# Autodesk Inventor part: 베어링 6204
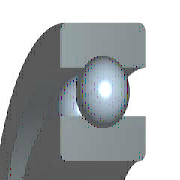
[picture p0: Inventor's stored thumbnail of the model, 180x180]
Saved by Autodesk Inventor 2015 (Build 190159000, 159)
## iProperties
Created: 2012-02
Part Number: 베어링 6204
Material: 강철, 연강
Description: 깊은 그루브 볼 베어링
Document SubType Name: Modeling
Standard: KS B 2023
Designer: mduedu
Standards Organization: KS
Language: ko-KR
Size Designation: 6203 - 17 x 40 x 12
Categories: <MemberInstance><Categories><Category DisplayName="샤프트 부품" InternalName="7f7aeb1f-a693-4053-b835-cee3144e0d98" Mnemonic="SHFT"><Category DisplayName="베어링" Inter
Density: 1 g/cm^3
Appearance: 노란색
IsCustomPart: 1
Author: mduedu
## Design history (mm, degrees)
sketch "스케치" dims "d0" = 7.02 (= -0.26 x WD + 0.26 x BD)
  geometry: L1 (3.49, 16.75)-(10.51, 16.75); L2 (7, 16.75)-(7, 13.24); L3 (7, 16.75)-(7, 20.26); L4 (4.392, 14.401)-(0, 14.401); L5 (0, 10)-(14, 10); L6 (4.392, 19.099)-(0, 19.099); L7 (0, 23.5)-(14, 23.5); L8 (14, 10)-(14, 14.401); L9 (9.608, 14.401)-(14, 14.401); L10 (9.608, 19.099)-(14, 19.099); L11 (14, 23.5)-(14, 19.099); L12 (-2.4, 0)-(14.4, 0) reference; L13 (0, 7.3)-(0, 26.2) reference
  constraints: 22 end point, 4 point on line, 2 collinear, 2 perpendicular, 2 symmetric about line, 1 midpoint, 1 parallel, 14 other
  dimensions: "d9" = 20 diameter of L5 L12 (= WD); "d11" = 47 diameter of L7 L12 (= BD); "d12" = 14 distance between parallel lines of L8 L13 (= KB); "d13" = 28.802 diameter of L9 L12 (= 0.326 x BD + 0.674 x WD)
revolve "본체" stored, may be unused: angle "d6" = 90 deg
revolve "볼" stored, may be unused: angle "d7" = 90 deg
pattern_circular "IDS_ARRAYBALL[SIMPL:T]" dims angle "d3" = 360 deg
body "Solid1"
fillet "모깎기1" dims "d1" = 1 (= KRS)
other parameters: "WD" = 20 [user parameter; used in 5 equation terms], "BD" = 47 [user parameter; used in 5 equation terms], "KB" = 14 [user parameter; used in 1 equation term], "KRS" = 1 [user parameter; used in 1 equation term], "d4" = 0, "d5" = 0, "d8" = 0, "d14" = 0, "d15" = 0, "BBA" = 0 [user parameter], "BC0" = 4750000 [user parameter], "BC" = 9560000 [user parameter], "BR" = 23.5 (= 0.5 x BD) [user parameter]
